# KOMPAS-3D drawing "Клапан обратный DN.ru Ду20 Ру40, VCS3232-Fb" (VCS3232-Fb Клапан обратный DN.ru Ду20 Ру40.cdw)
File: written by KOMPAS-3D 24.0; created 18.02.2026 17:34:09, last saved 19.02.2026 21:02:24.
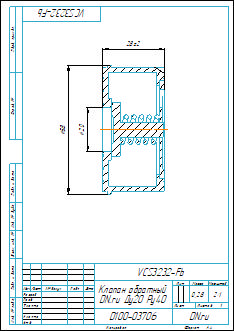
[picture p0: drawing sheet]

Document properties: v313: 1; D: 58; d: 20; a: 1; L: 28; Артикул: D100-03706; Автор: R2D2; Форматы листов документа: A4; Полное имя файла: VCS3232-Fb Клапан обратный DN.ru Ду20 Ру40.m3d; Масса: 0.28; Наименование: Клапан обратный DN.ru Ду20 Ру40; Количество листов документа: 1; Примечание: D100-03706

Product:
- Body: Тело 1  | qty 1
    Масса: 0.149728
- Body: Тело 2  | qty 1
    Масса: 0.03963
- Part/product: Клапан обратный DN.ru Ду20 Ру40  | designation VCS3232-Fb
    Масса: 0.28
    Примечание: D100-03706
    additional columns: 1; D100-03706

Views: Вид 1, Местный разрез 2, Справа
Referenced files in E:\Работа\Зайцев\VCS3232-Fb Клапан обратный DN.ru Ду15-100\DN20\: VCS3232-Fb Клапан обратный DN.ru Ду20 Ру40.m3d
Referenced files in E:\Работа\Зайцев\VCS3232-Fb Клапан обратный DN.ru Ду15-100\DN15\: VCS3232-Fb Клапан обратный DN.ru Ду15 Ру40.m3d
Referenced files in E:\Работа\Зайцев\Для компаса\: чертеж DN.ru.cdt
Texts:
  VCS3232-Fb
  чертеж DN.ru.cdt
  Клапан обратный
  DN.ru Ду20 Ру40
  prop
  Клапан обратный DN.ru Ду20 Ру40
  VCS3232-Fb Клапан обратный DN.ru Ду20 Ру40
Dimensions and other numbers on the sheet: 0; 3; 2; 4; 28±2; 20; 58; 6; 2:1; 1; 0,28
